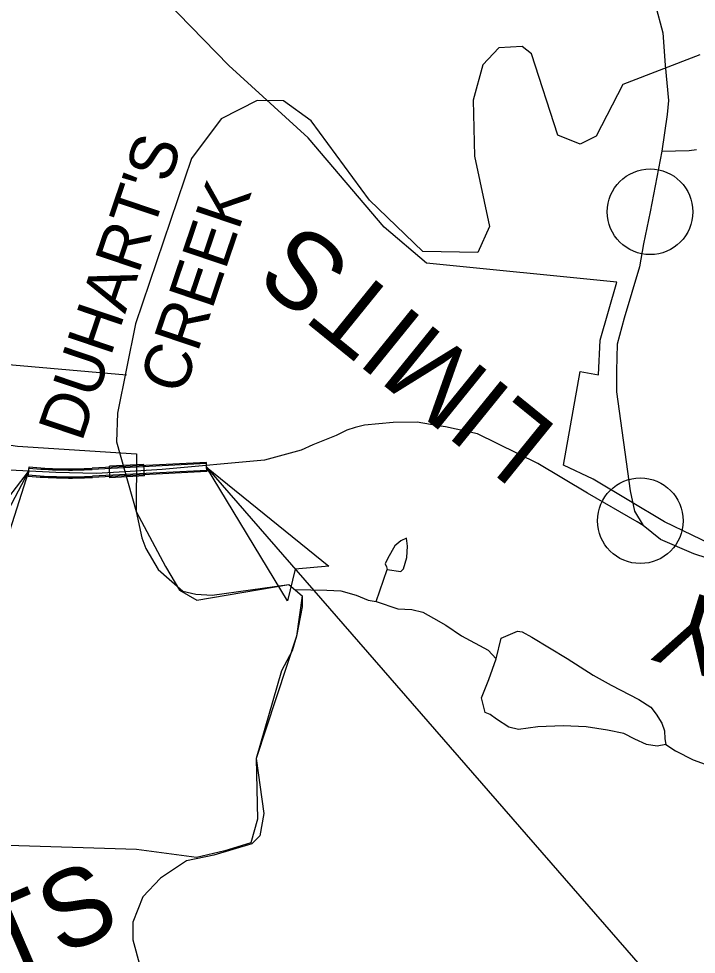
# Model space of a CAD drawing. Extents: x 1372027 to 1374286, y 553832 to 556743.
# Drawn here: x 1373297 to 1373346.9, y 554175.8 to 554244.7 of the extents above; entities that cross this region are included whole.
import ezdxf

# ---------------------------------------------------------------- set-up
doc = ezdxf.new("R2010")
doc.units = 0
for name, color, linetype in [('Prop Dimension', 7, 'Continuous'), ('Prop Dimension Text', 7, 'Continuous'), ('Prop EOT', 7, 'Continuous'), ('Prop Horizontal Alignment Tick Small', 7, 'Continuous'), ('Prop Paved Shoulder', 7, 'Continuous'), ('Prop Roadway Bridge', 7, 'Continuous'), ('Prop Terminator CELL', 7, 'Continuous'), ('Sheet Clip Boundary CELL', 7, 'Continuous'), ('Sheet Plot Border Outside CELL', 7, 'Continuous'), ('Sheet Sticker Preliminary CELL', 7, 'Continuous')]:
    doc.layers.add(name, color=color, linetype=linetype)

msp = doc.modelspace()

# ---------------------------------------------------------------- linework, layer by layer
at = {"layer": 'Prop Dimension'}
for p, q in [((1373297.698, 554211.343), (1373265.721, 554150.896)), ((1373310.791, 554211.654), (1373352.145, 554164.188))]:
    msp.add_line(p, q, dxfattribs=at)
msp.add_lwpolyline([(1373347.132, 554242.004), (1373341.457, 554239.817), (1373339.499, 554236.019), (1373338.319, 554235.428), (1373336.673, 554236.081), (1373334.726, 554242.067), (1373334.047, 554242.614), (1373332.314, 554242.504), (1373331.149, 554241.25), (1373330.432, 554238.653), (1373330.521, 554234.533), (1373331.643, 554229.362), (1373330.779, 554227.452), (1373326.713, 554227.536), (1373322.79, 554231.295), (1373318.497, 554237.154), (1373316.459, 554238.603), (1373314.53, 554238.643), (1373311.881, 554237.3), (1373309.686, 554234.361), (1373305.581, 554222.201), (1373304.235, 554215.628), (1373304.175, 554213.532), (1373305.607, 554208.403), (1373306.032, 554206.466), (1373306.332, 554205.687), (1373307.231, 554204.13), (1373309.054, 554202.535), (1373310.019, 554202.309), (1373311.218, 554202.249), (1373316.87, 554203.031), (1373317.832, 554202.205), (1373317.832, 554201.378), (1373317.431, 554199.229), (1373317.11, 554198.155), (1373316.309, 554196.667), (1373314.465, 554190.221), (1373315.03, 554186.177), (1373314.731, 554184.544), (1373314.144, 554183.94), (1373311.339, 554183.114), (1373309.335, 554182.7), (1373307.42, 554181.43), (1373306.102, 554180.053), (1373305.383, 554178.196), (1373305.383, 554176.879), (1373305.922, 554174.903)], dxfattribs=at)
at = {"layer": 'Prop Dimension Text'}
for p, q in [((1373314.545, 554185.758), (1373314.064, 554184.023)), ((1373305.647, 554183.527), (1373286.769, 554184.105)), ((1373314.064, 554184.023), (1373312.14, 554183.444)), ((1373310.056, 554182.948), (1373305.647, 554183.527)), ((1373312.14, 554183.444), (1373310.056, 554182.948))]:
    msp.add_line(p, q, dxfattribs=at)
for points in [[(1373348.589, 554205.688), (1373344.519, 554207.628), (1373339.27, 554210.775), (1373337.07, 554211.815), (1373338.314, 554218.698), (1373339.658, 554218.467), (1373339.77, 554221.007), (1373341.001, 554225.278), (1373327.007, 554226.663), (1373323.872, 554229.318), (1373318.274, 554235.897), (1373312.453, 554241.206), (1373306.855, 554246.978), (1373304.056, 554251.479), (1373300.809, 554247.67), (1373274.885, 554248.238), (1373271.198, 554241.626), (1373266.228, 554233.279), (1373267.992, 554232.205), (1373269.845, 554229.371)], [(1373269.845, 554229.371), (1373268.232, 554228.32), (1373266.869, 554230.386), (1373264.864, 554231.281), (1373264.064, 554229.973), (1373259.013, 554221.378), (1373263.422, 554221.461), (1373270.133, 554221.411), (1373275.955, 554220.834), (1373278.306, 554219.795), (1373281.441, 554217.371), (1373284.128, 554215.409), (1373288.382, 554214.485), (1373296.891, 554213.216), (1373305.654, 554212.645), (1373305.607, 554208.403), (1373307.772, 554204.353), (1373308.814, 554202.618), (1373310.096, 554201.874), (1373316.87, 554203.031), (1373317.832, 554202.205), (1373317.431, 554199.229), (1373314.465, 554190.221), (1373314.545, 554185.758)]]:
    msp.add_lwpolyline(points, dxfattribs=at)
at = {"layer": 'Prop EOT'}
for p, q in [((1373297.666, 554211.009), (1373297.729, 554211.678)), ((1373310.793, 554211.929), (1373302.382, 554211.495)), ((1373310.819, 554211.426), (1373302.408, 554210.991)), ((1373310.806, 554211.678), (1373310.793, 554211.929)), ((1373310.819, 554211.426), (1373310.806, 554211.678))]:
    msp.add_line(p, q, dxfattribs=at)
for radius in [31.983, 32.487]:
    msp.add_arc((1373300.731, 554243.435), radius, 264.59986, 272.95848, dxfattribs=at)
at = {"layer": 'Prop Horizontal Alignment Tick Small'}
msp.add_line((1373297.698, 554211.343), (1373297.688, 554211.239), dxfattribs=at)
at = {"layer": 'Prop Paved Shoulder'}
for p, q in [((1373310.789, 554212.013), (1373302.378, 554211.579)), ((1373310.793, 554211.929), (1373310.789, 554212.013)), ((1373310.824, 554211.342), (1373302.413, 554210.907)), ((1373310.819, 554211.426), (1373310.824, 554211.342))]:
    msp.add_line(p, q, dxfattribs=at)
for points in [[(1373311.362, 554288.486), (1373312.132, 554286.015), (1373313.397, 554278.9), (1373314.195, 554275.841), (1373314.454, 554274.439), (1373315.137, 554272.919), (1373315.52, 554272.011), (1373316.743, 554270.792), (1373317.98, 554269.633), (1373318.763, 554268.881), (1373325.977, 554263.348), (1373337.959, 554254.546), (1373339.099, 554253.37), (1373340.402, 554251.733), (1373342.212, 554248.706), (1373343.05, 554247.409), (1373343.824, 554245.73), (1373344.386, 554243.621), (1373344.576, 554241.233)], [(1373344.576, 554241.233), (1373344.801, 554238.635), (1373344.711, 554237.605), (1373344.312, 554234.92)], [(1373344.312, 554234.92), (1373343.457, 554230.449), (1373342.968, 554228.098), (1373342.683, 554226.398), (1373341.543, 554222.62), (1373341.038, 554220.702), (1373340.973, 554218.758), (1373340.973, 554217.205), (1373341.988, 554209.916), (1373342.317, 554208.431), (1373342.955, 554207.36)], [(1373344.312, 554234.92), (1373346.339, 554234.967), (1373346.886, 554235.036)], [(1373304.792, 554211.321), (1373302.689, 554211.206), (1373299.707, 554211.266), (1373296.293, 554211.432), (1373293.238, 554211.936), (1373287.36, 554213.152), (1373286.39, 554213.343), (1373285.231, 554213.751), (1373283.39, 554214.297), (1373282.133, 554214.819), (1373280.254, 554215.864), (1373279.027, 554216.614), (1373277.322, 554217.568), (1373275.226, 554218.556), (1373272.414, 554219.421), (1373270.112, 554219.782), (1373265.817, 554219.85), (1373261.691, 554219.866), (1373259.035, 554219.898), (1373256.808, 554219.868)], [(1373342.955, 554207.36), (1373342.494, 554207.647), (1373338.839, 554209.742), (1373335.2, 554211.928), (1373330.75, 554214.107), (1373328.394, 554214.621), (1373327.864, 554214.707), (1373326.3, 554214.962), (1373324.535, 554214.955), (1373322.43, 554214.745), (1373321.75, 554214.591), (1373321.12, 554214.394), (1373320.352, 554213.989), (1373318.615, 554213.314), (1373317.767, 554212.911), (1373315.062, 554212.167), (1373307.527, 554211.482), (1373304.792, 554211.321)], [(1373384.492, 554194.664), (1373378.855, 554196.151), (1373369.62, 554198.764), (1373367.029, 554199.447), (1373364.834, 554199.969), (1373362.43, 554200.472), (1373358.013, 554201.869), (1373354.325, 554202.736), (1373351.997, 554203.545), (1373350.822, 554203.936), (1373346.685, 554205.278), (1373344.225, 554206.339), (1373342.955, 554207.36)]]:
    msp.add_lwpolyline(points, dxfattribs=at)
for radius in [31.899, 32.571]:
    msp.add_arc((1373300.731, 554243.435), radius, 264.59986, 272.95848, dxfattribs=at)
at = {"layer": 'Prop Roadway Bridge'}
for p, q in [((1373306.187, 554211.859), (1373303.643, 554211.728)), ((1373303.686, 554210.889), (1373303.643, 554211.728)), ((1373306.23, 554211.021), (1373306.187, 554211.859)), ((1373306.23, 554211.021), (1373303.686, 554210.889))]:
    msp.add_line(p, q, dxfattribs=at)
at = {"layer": 'Prop Terminator CELL'}
for points in [[(1373290.669, 554202.232), (1373297.698, 554211.343), (1373294.148, 554200.321), (1373293.043, 554202.544)], [(1373316.768, 554201.821), (1373310.791, 554211.654), (1373319.802, 554204.38), (1373317.33, 554204.148)], [(1373316.768, 554201.821), (1373310.791, 554211.654), (1373319.802, 554204.38), (1373317.33, 554204.148)]]:
    msp.add_lwpolyline(points, close=True, dxfattribs=at)
at = {"layer": 'Sheet Clip Boundary CELL'}
for centre in [(1373343.457, 554230.449), (1373342.74, 554207.721)]:
    msp.add_circle(centre, 3.15, dxfattribs=at)
at = {"layer": 'Sheet Plot Border Outside CELL'}
for p, q in [((1373344.571, 554241.232), (1373344.571, 554241.232)), ((1373304.766, 554211.33), (1373304.766, 554211.33))]:
    msp.add_line(p, q, dxfattribs=at)
at = {"layer": 'Sheet Sticker Preliminary CELL'}
msp.add_line((1373323.283, 554201.785), (1373324.088, 554204.122), dxfattribs=at)
for points in [[(1373282.004, 554221.492), (1373282.331, 554221.382), (1373282.658, 554221.273), (1373282.976, 554221.141), (1373283.285, 554220.991), (1373283.592, 554220.831), (1373283.896, 554220.67), (1373284.203, 554220.513), (1373284.516, 554220.371), (1373284.849, 554220.276), (1373285.188, 554220.224), (1373285.529, 554220.177), (1373285.872, 554220.134), (1373304.909, 554218.455)], [(1373324.088, 554204.122), (1373325.101, 554203.975), (1373325.312, 554204.182), (1373325.536, 554205.017), (1373325.605, 554205.855), (1373325.531, 554206.445), (1373325.096, 554206.242), (1373324.675, 554205.874), (1373324.156, 554204.961), (1373323.942, 554204.546), (1373324.058, 554204.333), (1373324.088, 554204.122)], [(1373317.298, 554202.663), (1373319.646, 554202.617), (1373320.696, 554202.552), (1373321.826, 554202.235), (1373322.698, 554201.882), (1373323.283, 554201.785)], [(1373323.283, 554201.785), (1373324.874, 554201.247), (1373325.925, 554201.183), (1373326.713, 554201), (1373327.515, 554200.563), (1373328.417, 554200.041), (1373329.573, 554199.26), (1373331.535, 554198.209), (1373332.131, 554197.559)], [(1373332.131, 554197.559), (1373332.49, 554199.082), (1373333.698, 554199.594), (1373334.043, 554199.544), (1373334.741, 554199.152), (1373337.364, 554197.585), (1373339.269, 554196.368), (1373340.598, 554195.628), (1373342.628, 554194.577), (1373343.512, 554194.011), (1373343.916, 554193.498), (1373344.316, 554192.818), (1373344.528, 554192.267), (1373344.551, 554191.679), (1373344.628, 554191.257)], [(1373344.628, 554191.257), (1373343.989, 554191.145), (1373343.199, 554191.246), (1373342.328, 554191.642), (1373341.526, 554192.077), (1373340.324, 554192.314), (1373338.761, 554192.555), (1373337.057, 554192.633), (1373335.194, 554192.547), (1373333.765, 554192.35), (1373333.046, 554192.529), (1373332.138, 554193.113), (1373331.68, 554193.46), (1373331.324, 554193.618), (1373331.055, 554194.693), (1373331.593, 554196.036), (1373332.131, 554197.559)], [(1373344.628, 554191.257), (1373345.326, 554190.781), (1373346.622, 554190.122), (1373347.786, 554189.72), (1373348.834, 554189.571), (1373350.643, 554189.537), (1373352.075, 554189.631), (1373353.25, 554189.817), (1373353.802, 554189.806), (1373354.711, 554189.619), (1373356.1, 554189.253), (1373357.022, 554188.856), (1373357.837, 554188.21), (1373359.12, 554186.923), (1373359.953, 554186.316), (1373360.687, 554185.965), (1373361.607, 554185.483), (1373362.562, 554184.959), (1373363.766, 554183.969), (1373365.249, 554182.339), (1373366.194, 554181.353), (1373366.998, 554180.205), (1373367.642, 554178.802), (1373368.527, 554176.515)]]:
    msp.add_lwpolyline(points, dxfattribs=at)

# ---------------------------------------------------------------- texts
at = {"layer": 'Prop Dimension'}
for s, p in [("DUHART'S ", (1373301.609, 554213.442)), ('CREEK', (1373309.067, 554216.883))]:
    msp.add_text(s, height=3.4449, rotation=71.34319, dxfattribs=at).set_placement(p)
at = {"layer": 'Sheet Clip Boundary CELL'}
for s, rotation, p in [('LIMITS', 140.97762, (1373336.801, 554214.461)), ('CITY', 162.75943, (1373361.503, 554197.848)), ('LIMITS', 23.26575, (1373282.21, 554168.045))]:
    msp.add_text(s, height=5.67, rotation=rotation, dxfattribs=at).set_placement(p)

doc.saveas('drawing.dxf')
